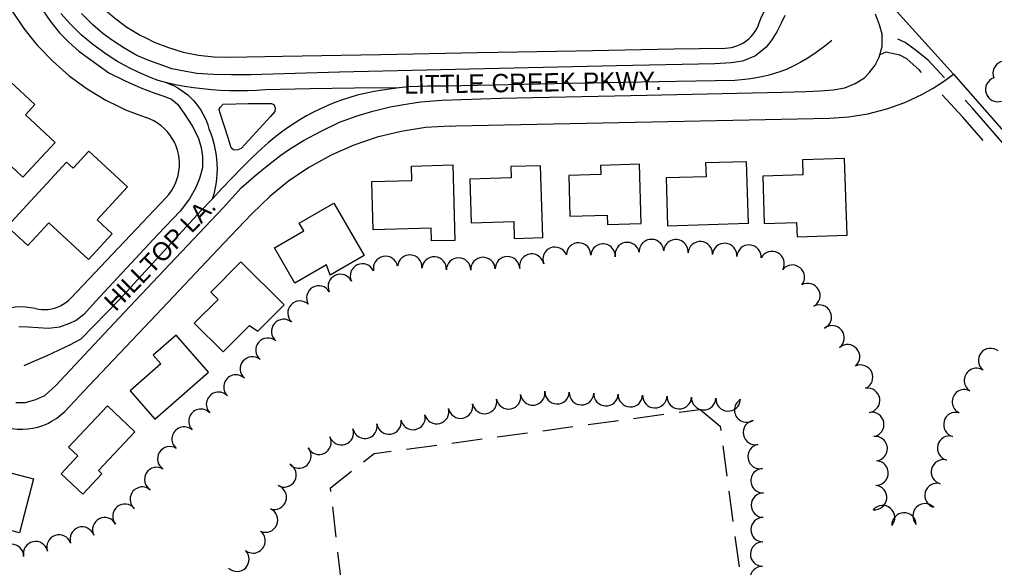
# Model space of a CAD drawing. Extents: x -25029 to 2274964, y -81170 to 687028.
# Drawn here: x -14288 to -13491, y -66632 to -66184 of the extents above; entities that cross this region are included whole.
import ezdxf

# ---------------------------------------------------------------- set-up
doc = ezdxf.new("R2010")
doc.units = 0
for name, color, linetype in [('81911BEA - RW_X_Fee_RW', 7, 'Continuous'), ('BLDG', 7, 'Continuous'), ('DRIVWY', 7, 'Continuous'), ('GE_X_CL_2000', 7, 'Continuous'), ('RECREATION', 7, 'Continuous'), ('ROAD', 7, 'Continuous'), ('ROAD-NAME', 7, 'Continuous'), ('TREES', 7, 'Continuous')]:
    doc.layers.add(name, color=color, linetype=linetype)

msp = doc.modelspace()

# ---------------------------------------------------------------- linework, layer by layer
at = {"layer": '81911BEA - RW_X_Fee_RW'}
for p, q in [((-13581.33, -66165.9), (-13524.59, -66228.63)), ((-14246.44, -66411.89), (-14168.5, -66329.68))]:
    msp.add_line(p, q, dxfattribs=at)
for points in [[(-14324.71, -66074), (-14323.56, -66091.93), (-14320.84, -66109.69), (-14316.58, -66127.14), (-14313.09, -66137.43), (-14310.81, -66144.16), (-14303.57, -66160.6), (-14294.91, -66176.35), (-14284.91, -66191.27), (-14276.29, -66201.99), (-14273.64, -66205.27), (-14261.19, -66218.22), (-14247.66, -66230.04), (-14233.14, -66240.62), (-14217.75, -66249.89), (-14207.78, -66254.76), (-14201.6, -66257.78), (-14184.83, -66264.23)], [(-14264.73, -66072.77), (-14263.92, -66085.4), (-14262.01, -66097.9), (-14259.02, -66110.19), (-14254.97, -66122.18), (-14249.89, -66133.76), (-14243.82, -66144.86), (-14236.81, -66155.39), (-14228.9, -66165.27), (-14220.17, -66174.42), (-14210.67, -66182.77), (-14200.48, -66190.26), (-14189.67, -66196.84), (-14184.53, -66199.38), (-14178.33, -66202.45), (-14166.55, -66207.05), (-14154.41, -66210.61), (-14142.01, -66213.09), (-14129.43, -66214.49), (-14116.79, -66214.78)], [(-13683.42, -66186.81), (-13681.55, -66181.9), (-13679.27, -66177.17), (-13676.58, -66172.66), (-13673.51, -66168.41), (-13670.07, -66164.44), (-13666.31, -66160.78), (-13662.23, -66157.47), (-13657.89, -66154.52), (-13653.3, -66151.97), (-13648.51, -66149.83), (-13643.54, -66148.11), (-13638.45, -66146.84), (-13633.27, -66146.01), (-13628.03, -66145.65), (-13622.78, -66145.74), (-13617.56, -66146.29), (-13612.41, -66147.29), (-13607.36, -66148.74), (-13602.46, -66150.62), (-13597.75, -66152.93), (-13593.25, -66155.64), (-13589.01, -66158.73), (-13584.92, -66162.07)], [(-13711.29, -66207.39), (-13708.66, -66207.22), (-13706.05, -66206.82), (-13703.49, -66206.19), (-13700.99, -66205.34), (-13698.58, -66204.28), (-13696.27, -66203), (-13694.08, -66201.53), (-13692.03, -66199.87), (-13690.13, -66198.04), (-13688.4, -66196.05), (-13686.86, -66193.91), (-13685.5, -66191.65), (-13684.35, -66189.27), (-13683.42, -66186.81)], [(-14116.79, -66214.78), (-14073.21, -66213.99), (-13993.23, -66212.53), (-13913.24, -66211.07), (-13833.25, -66209.61), (-13753.26, -66208.15), (-13711.29, -66207.39)], [(-13549.93, -66245.05), (-13541.16, -66240.08), (-13532.71, -66234.6), (-13524.59, -66228.63)], [(-13524.59, -66228.63), (-13386.09, -66386.37), (-13201.11, -66597.05)], [(-13626.11, -66264.78), (-13614.4, -66263.99), (-13610.27, -66263.71), (-13594.6, -66261.18), (-13579.23, -66257.2), (-13564.3, -66251.81), (-13549.93, -66245.05)], [(-14168.5, -66329.68), (-14166.22, -66327.04), (-14164.17, -66324.22), (-14162.37, -66321.23), (-14160.84, -66318.09), (-14159.59, -66314.84), (-14158.63, -66311.48), (-14157.97, -66308.06), (-14157.6, -66304.59), (-14157.54, -66301.1), (-14157.79, -66297.62), (-14158.33, -66294.18), (-14159.18, -66290.79), (-14160.31, -66287.49), (-14161.73, -66284.31), (-14163.43, -66281.26), (-14165.38, -66278.36), (-14167.57, -66275.65), (-14170, -66273.14), (-14172.63, -66270.85), (-14175.45, -66268.8), (-14178.44, -66267.01), (-14181.58, -66265.48), (-14184.83, -66264.23)], [(-13936.07, -66271.11), (-13931.54, -66271.02), (-13851.56, -66269.38), (-13771.57, -66267.75), (-13691.59, -66266.11), (-13626.11, -66264.78)], [(-13936.07, -66271.11), (-13956.25, -66272.41), (-13976.23, -66275.48), (-13995.88, -66280.29), (-14015.02, -66286.81), (-14033.52, -66294.99), (-14043.9, -66300.72), (-14051.22, -66304.76), (-14068, -66316.05), (-14083.72, -66328.76), (-14098.27, -66342.81)], [(-14251.43, -66504.36), (-14231.51, -66483.34), (-14176.46, -66425.29), (-14121.42, -66367.23), (-14098.27, -66342.81)], [(-14275.21, -66420.42), (-14272.64, -66420.92), (-14270.03, -66421.19), (-14267.42, -66421.23), (-14264.81, -66421.05), (-14262.22, -66420.64), (-14259.68, -66420.01), (-14257.21, -66419.15), (-14254.82, -66418.09), (-14252.53, -66416.82), (-14250.36, -66415.35), (-14248.32, -66413.7), (-14246.44, -66411.89)], [(-14275.21, -66420.42), (-14279.34, -66419.61), (-14283.53, -66419.15), (-14287.74, -66419.05), (-14291.95, -66419.3), (-14296.12, -66419.9), (-14300.22, -66420.86), (-14304.23, -66422.15), (-14308.12, -66423.78), (-14311.85, -66425.73), (-14315.41, -66427.99), (-14318.71, -66430.5)], [(-14298.61, -66517.63), (-14294.43, -66518.45), (-14290.19, -66518.92), (-14285.92, -66519.02), (-14281.66, -66518.76), (-14277.44, -66518.14), (-14273.29, -66517.16), (-14269.23, -66515.83), (-14265.3, -66514.17), (-14261.53, -66512.17), (-14257.95, -66509.85), (-14254.57, -66507.25), (-14251.43, -66504.36)]]:
    msp.add_lwpolyline(points, dxfattribs=at)
at = {"layer": 'BLDG'}
for points in [[(-14299.71, -66231.19), (-14275.69, -66253.65), (-14283.37, -66261.86), (-14259.2, -66284.46), (-14285.76, -66312.87), (-14333.95, -66267.81)], [(-14281.61, -66368.73), (-14264.46, -66350.18), (-14232.02, -66380.18), (-14212.56, -66359.13), (-14224.87, -66347.74), (-14200.02, -66320.87), (-14231.64, -66291.62), (-14244.58, -66305.62), (-14249.86, -66300.73), (-14298.39, -66353.21)], [(-13813.22, -66303.42), (-13812.98, -66310.85), (-13839.29, -66311.66), (-13838.26, -66344.81), (-13807.74, -66343.86), (-13807.5, -66351.65), (-13779.89, -66350.79), (-13781.39, -66302.43)], [(-13693.82, -66300.3), (-13727.31, -66301.34), (-13726.96, -66312.56), (-13759.56, -66313.57), (-13758.35, -66352.66), (-13692.26, -66350.6)], [(-13648.21, -66298.68), (-13647.83, -66311.05), (-13680.56, -66312.07), (-13679.36, -66350.7), (-13652.91, -66349.88), (-13652.54, -66361.61), (-13611.68, -66360.34), (-13613.63, -66297.6)], [(-14000.23, -66316.35), (-13967.57, -66315.52), (-13967.86, -66303.82), (-13933.91, -66302.95), (-13932.34, -66364.59), (-13951.57, -66365.08), (-13951.83, -66354.68), (-13999.22, -66355.89)], [(-13886.64, -66304.3), (-13886.35, -66313.44), (-13920.01, -66314.48), (-13918.9, -66350.2), (-13884.21, -66349.12), (-13883.78, -66362.97), (-13860.4, -66362.24), (-13862.22, -66303.54)], [(-14055.97, -66356.92), (-14059.66, -66350.55), (-14031.42, -66334.17), (-14006.61, -66376.93), (-14034.44, -66393.06), (-14037.42, -66384.72), (-14063.16, -66399.65), (-14079.9, -66370.8)], [(-14132.04, -66406.82), (-14126.04, -66412.81), (-14145.43, -66432.22), (-14121.84, -66455.8), (-14100.17, -66434.1), (-14093.47, -66438.69), (-14072.02, -66417.21), (-14107.25, -66382.01)], [(-14179.05, -66458.43), (-14172.77, -66465.63), (-14197.84, -66487.51), (-14177.66, -66510.63), (-14133.79, -66472.33), (-14160.25, -66442.02)], [(-14193.98, -66521.1), (-14223.8, -66552.73), (-14221.01, -66555.36), (-14236.68, -66571.99), (-14254.33, -66555.34), (-14240.61, -66540.78), (-14248.17, -66533.65), (-14216.41, -66499.95)], [(-14318.47, -66525.26), (-14325.88, -66553.96), (-14307.67, -66558.66), (-14307.5, -66551.65), (-14276.86, -66559.55), (-14288.25, -66603.7), (-14339.04, -66590.6), (-14342.06, -66602.3), (-14367.94, -66595.63), (-14347.84, -66517.69)]]:
    msp.add_lwpolyline(points, close=True, dxfattribs=at)
at = {"layer": 'DRIVWY'}
for points in [[(-13531.97, -66231.63), (-13545.18, -66217.24), (-13555.84, -66208.81), (-13564.24, -66202.92), (-13570.24, -66200.13)], [(-13550.64, -66227.25), (-13552.55, -66225.17), (-13562.77, -66216.11), (-13568.58, -66213.07), (-13579.92, -66210.86), (-13584.9, -66212.93)], [(-13500.38, -66282.91), (-13517.02, -66263.9), (-13533.74, -66245.67)], [(-13481.98, -66287.54), (-13509.02, -66256.64), (-13515.06, -66250.05)]]:
    msp.add_lwpolyline(points, dxfattribs=at)
at = {"layer": 'GE_X_CL_2000'}
for points in [[(-14167.89, -66235.78), (-14174.86, -66233.78), (-14180.63, -66231.67), (-14186.32, -66229.36), (-14191.94, -66226.87), (-14197.47, -66224.19), (-14202.9, -66221.33), (-14208.24, -66218.28), (-14213.47, -66215.06), (-14218.59, -66211.67), (-14223.6, -66208.11), (-14228.48, -66204.39), (-14233.24, -66200.5), (-14237.86, -66196.46), (-14242.34, -66192.27), (-14246.68, -66187.93), (-14254.66, -66179.12)], [(-13624.02, -66201.17), (-13628.84, -66205.13), (-13633.81, -66208.89), (-13638.92, -66212.46), (-13644.17, -66215.82), (-13649.55, -66218.98), (-13655.05, -66221.92), (-13660.66, -66224.64), (-13665.83, -66226.53), (-13671.07, -66228.22), (-13676.37, -66229.7), (-13681.73, -66230.97), (-13687.13, -66232.01), (-13692.57, -66232.84), (-13698.04, -66233.46), (-13703.53, -66233.85), (-13751.17, -66234.67), (-13837.9, -66236.31), (-13939.14, -66238.61), (-13946.9, -66238.43), (-13954.67, -66238.47), (-13962.43, -66238.73), (-13970.18, -66239.21), (-13977.91, -66239.9)], [(-14167.89, -66235.78), (-14161.81, -66238.4), (-14158.9, -66239.98), (-14156.09, -66241.73), (-14153.39, -66243.65), (-14150.81, -66245.74), (-14148.36, -66247.97), (-14146.05, -66250.35), (-14143.89, -66252.87), (-14141.88, -66255.51), (-14140.05, -66258.27), (-14138.38, -66261.14), (-14136.88, -66264.1), (-14135.57, -66267.15), (-14134.45, -66270.27), (-14133.52, -66273.45), (-14131.96, -66277.35), (-14130.6, -66281.32), (-14129.45, -66285.35), (-14128.5, -66289.44), (-14127.77, -66293.57), (-14127.24, -66297.73), (-14126.93, -66301.92), (-14126.84, -66306.11), (-14126.95, -66310.31), (-14127.28, -66314.49), (-14127.83, -66318.65), (-14128.59, -66322.78), (-14129.55, -66326.86), (-14130.73, -66330.88)], [(-13977.91, -66239.9), (-14014.35, -66240.22), (-14050.79, -66240.76), (-14087.21, -66241.54), (-14094.58, -66242.05), (-14101.95, -66242.36), (-14109.34, -66242.46), (-14116.72, -66242.35), (-14124.1, -66242.04), (-14131.46, -66241.51), (-14138.81, -66240.78), (-14146.13, -66239.84), (-14153.42, -66238.69), (-14160.68, -66237.34), (-14167.89, -66235.78)], [(-13977.91, -66239.9), (-13993.31, -66241.95), (-13999.62, -66243.08), (-14005.89, -66244.44), (-14012.11, -66246), (-14018.27, -66247.79), (-14024.37, -66249.79), (-14030.39, -66251.99), (-14036.33, -66254.41), (-14042.19, -66257.03), (-14047.95, -66259.85), (-14053.61, -66262.86), (-14059.16, -66266.08), (-14064.59, -66269.48), (-14069.91, -66273.07), (-14075.09, -66276.84), (-14080.15, -66280.79), (-14085.06, -66284.91), (-14089.83, -66289.2), (-14098.33, -66297.21), (-14106.67, -66305.39), (-14114.85, -66313.73), (-14122.87, -66322.23), (-14130.73, -66330.88)], [(-14130.73, -66330.88), (-14139.68, -66340.19), (-14206.77, -66413.19), (-14238.29, -66445.44), (-14247.44, -66450.16), (-14256.67, -66454.69), (-14266, -66459.04), (-14275.42, -66463.19), (-14284.91, -66467.14)]]:
    msp.add_lwpolyline(points, dxfattribs=at)
at = {"layer": 'RECREATION'}
for p, q in [((-13786.2, -66510.15), (-13761.43, -66506.79)), ((-13749.04, -66505.11), (-13731.89, -66502.78)), ((-13860.52, -66520.23), (-13835.75, -66516.87)), ((-13823.36, -66515.19), (-13798.59, -66511.83)), ((-13897.68, -66525.27), (-13872.91, -66521.91)), ((-13972, -66535.35), (-13947.23, -66531.99)), ((-13934.84, -66530.31), (-13910.07, -66526.95)), ((-13713.3, -66532.45), (-13709.97, -66557.23)), ((-13708.3, -66569.62), (-13704.97, -66594.39)), ((-14029.39, -66607.14), (-14032.25, -66582.31)), ((-13703.31, -66606.78), (-13699.98, -66631.56)), ((-14025.09, -66644.4), (-14027.96, -66619.56))]:
    msp.add_line(p, q, dxfattribs=at)
for points in [[(-13731.89, -66502.78), (-13715.44, -66516.54), (-13714.97, -66520.06)], [(-14006.95, -66545.62), (-13998.39, -66538.93), (-13984.38, -66537.03)], [(-14033.68, -66569.89), (-14034.04, -66566.79), (-14016.8, -66553.32)]]:
    msp.add_lwpolyline(points, dxfattribs=at)
at = {"layer": 'ROAD'}
for points in [[(-14269.03, -66176.97), (-14263.02, -66185.79), (-14255.79, -66194.92), (-14248.23, -66202.18), (-14239.74, -66210.05), (-14225.1, -66220.66), (-14215.29, -66227.68), (-14202.07, -66234.28), (-14189.27, -66240.01), (-14177.73, -66244.33), (-14170.27, -66246.74), (-14164.11, -66249.27), (-14159.07, -66253.22), (-14153.61, -66260.8), (-14146.57, -66271.81), (-14142.1, -66281.31), (-14139.89, -66288.74), (-14138.68, -66295.92), (-14138.83, -66305.24), (-14141.13, -66314.08), (-14144.12, -66321.24), (-14149.26, -66330.73), (-14156.94, -66340.6), (-14175.24, -66359.68), (-14226.13, -66414.58), (-14235.7, -66425.2), (-14242.11, -66430.03), (-14248.31, -66432.78), (-14255.75, -66435.57), (-14264.67, -66436.58), (-14273.04, -66436.17), (-14281.56, -66435.46), (-14288.93, -66435.22)], [(-13662.56, -66180.72), (-13665.53, -66187.01), (-13668.94, -66194.01), (-13673.29, -66200.71), (-13677.84, -66206.53), (-13686.54, -66213.62), (-13697.27, -66218.14), (-13706.48, -66219.51), (-13719.8, -66220.28), (-13800.08, -66222), (-13920.14, -66224.67), (-14026.75, -66227.21), (-14099.23, -66229.26), (-14115.14, -66229.32), (-14129.66, -66229.12), (-14143.23, -66228.23), (-14153.74, -66226.31), (-14163.81, -66224.27), (-14171.12, -66221.71), (-14182.74, -66217.68), (-14192.33, -66213.55), (-14202.31, -66207.75), (-14212.21, -66201.3), (-14220.16, -66195.4), (-14228.31, -66188.41), (-14237.78, -66179.01)], [(-14026.56, -66267.99), (-14012.19, -66262.76), (-13999.53, -66259.08), (-13985.2, -66255.52), (-13970.9, -66252.96), (-13960.45, -66251.26), (-13943.07, -66249.93), (-13894.75, -66248.25), (-13775.49, -66245.79), (-13664.55, -66243.56), (-13645.3, -66243), (-13633.65, -66242.34), (-13623.08, -66241.43), (-13613.42, -66239.78), (-13604.95, -66236.29), (-13597.47, -66231.77), (-13593.69, -66227.67), (-13588.77, -66221.28), (-13585.44, -66214.85), (-13582.99, -66206.09), (-13583.04, -66196.11), (-13585.1, -66188.33), (-13588.36, -66179.58)], [(-14291.4, -66497.04), (-14283.44, -66497.01), (-14275.07, -66494.6), (-14267.77, -66491.38), (-14258.54, -66483.28), (-14235.47, -66458.38), (-14202.55, -66423.37), (-14165.63, -66384.2), (-14121.82, -66337.88), (-14107.12, -66321.6), (-14094.58, -66310.77), (-14084.55, -66302.69), (-14074.54, -66295.05), (-14067.56, -66290.15), (-14056.04, -66282.83), (-14041.62, -66275.29), (-14026.56, -66267.99)]]:
    msp.add_lwpolyline(points, dxfattribs=at)
msp.add_lwpolyline([(-14101.3, -66252.78), (-14082.22, -66252.58), (-14080.29, -66253.64), (-14079.41, -66256.19), (-14079.7, -66259.22), (-14083.12, -66263.4), (-14107.15, -66289.36), (-14109.93, -66290.6), (-14113.19, -66290.74), (-14115.17, -66289.03), (-14117.8, -66280.87), (-14124.6, -66259.75), (-14124.98, -66257.28), (-14124.22, -66255.93), (-14121.84, -66253.16)], close=True, dxfattribs=at)
at = {"layer": 'TREES'}
for centre, start, end in [((-13482.31, -66227.92), 22.60913, 202.60913), ((-13488.43, -66241.27), 108.17007, 288.17007), ((-13831.14, -66376.52), 359.03704, 179.03704), ((-13791.37, -66376.24), 10.9669, 190.9669), ((-13771.58, -66373.73), 3.46887, 183.46887), ((-13751.63, -66373.93), 355.39339, 175.39339), ((-13731.69, -66375.47), 355.75903, 175.75903), ((-13850.41, -66380.08), 21.91223, 201.91223), ((-13811.17, -66377.41), 355.83641, 175.83641), ((-13711.74, -66376.95), 355.75903, 175.75903), ((-13691.79, -66378.31), 356.43294, 176.43294), ((-13672.98, -66383.63), 332.01492, 152.01492), ((-13989.02, -66387.61), 10.77424, 190.77424), ((-13969.22, -66386.5), 355.61782, 175.61782), ((-13949.28, -66388.03), 355.61782, 175.61782), ((-13929.31, -66388.85), 359.66737, 179.66737), ((-13909.32, -66388.43), 2.74402, 182.74402), ((-13889.33, -66387.76), 1.09303, 181.09303), ((-13869.51, -66385.69), 10.81908, 190.81908), ((-14007.88, -66393.74), 25.24584, 205.24584), ((-13656.43, -66394.68), 320.53271, 140.53271), ((-14025.97, -66402.27), 25.24584, 205.24584), ((-14043.6, -66411.68), 30.94459, 210.94459), ((-13643.69, -66409.69), 300.07669, 120.07669), ((-14059.02, -66424.11), 46.79638, 226.79638), ((-13634.37, -66427.36), 295.57009, 115.57009), ((-14072.29, -66439.06), 50.00542, 230.00542), ((-13623.92, -66444.28), 307.81261, 127.81261), ((-14085.15, -66454.38), 50.00542, 230.00542), ((-13611.25, -66459.75), 310.7958, 130.7958), ((-13494.26, -66462.86), 52.47631, 232.47631), ((-14098, -66469.7), 50.00542, 230.00542), ((-13600.58, -66476.42), 294.46406, 114.46406), ((-13505.86, -66479.13), 56.58168, 236.58168), ((-14111.41, -66484.52), 45.71734, 225.71734), ((-13594.84, -66495.4), 279.19365, 99.19365), ((-14125.6, -66498.61), 43.87047, 223.87047), ((-13888.4, -66492.52), 190.9008, 10.9008), ((-13868.67, -66489.29), 187.68418, 7.68418), ((-13848.77, -66488.35), 177.71804, 357.71804), ((-13828.78, -66489.15), 177.71804, 357.71804), ((-13808.8, -66489.94), 177.71804, 357.71804), ((-13788.82, -66490.74), 177.71804, 357.71804), ((-13768.83, -66491.53), 177.71804, 357.71804), ((-13748.85, -66492.33), 177.71804, 357.71804), ((-13728.86, -66493.13), 177.71804, 357.71804), ((-13708.89, -66494.16), 176.35814, 356.35814), ((-13515.68, -66496.5), 64.42026, 244.42026), ((-13947.16, -66504.55), 194.96492, 14.96492), ((-13927.68, -66500.08), 190.9008, 10.9008), ((-13908.04, -66496.3), 190.9008, 10.9008), ((-13693.68, -66503.32), 121.53921, 301.53921), ((-14140.02, -66512.47), 43.87047, 223.87047), ((-13966.57, -66509.37), 192.88382, 12.88382), ((-13591.44, -66515.1), 280.40597, 100.40597), ((-13522.66, -66515.16), 74.56579, 254.56579), ((-14153.71, -66527.02), 49.56964, 229.56964), ((-14005.9, -66516.53), 191.6584, 11.6584), ((-13986.21, -66513.05), 188.37485, 8.37485), ((-13686.55, -66521.66), 100.9274, 280.9274), ((-14043.5, -66529.64), 206.7851, 26.7851), ((-14025.13, -66521.84), 199.21958, 19.21958), ((-13588.64, -66534.89), 275.66285, 95.66285), ((-13527.83, -66534.48), 75.44856, 255.44856), ((-14165.48, -66543.12), 58.12027, 238.12027), ((-13682.76, -66541.3), 100.9274, 280.9274), ((-14059.87, -66540.83), 221.92504, 41.92504), ((-14072.08, -66556.3), 241.47583, 61.47583), ((-13587.89, -66554.84), 268.64885, 88.64885), ((-13532.86, -66553.84), 75.44856, 255.44856), ((-14176.12, -66560.05), 57.59094, 237.59094), ((-13680.35, -66561.1), 92.94519, 272.94519), ((-14080.04, -66574.56), 251.47094, 71.47094), ((-13589.14, -66574.79), 264.16797, 84.16797), ((-13538.03, -66573.16), 74.55644, 254.55644), ((-14187.91, -66576.16), 49.9932, 229.9932), ((-13680, -66581.09), 89.05938, 269.05938), ((-14202.06, -66590.17), 39.44428, 219.44428), ((-13582.58, -66591.25), 319.31499, 139.31499), ((-13547.86, -66589.77), 44.25943, 224.25943), ((-14087.21, -66593.21), 246.46533, 66.46533), ((-13565.01, -66597.26), 2.92108, 182.92108), ((-14218.7, -66601.05), 26.90545, 206.90545), ((-13680.33, -66601.09), 89.05938, 269.05938), ((-14256, -66615.29), 18.90623, 198.90623), ((-14237.08, -66608.81), 18.90623, 198.90623), ((-14097.41, -66610.22), 231.63885, 51.63885), ((-14294.98, -66622.87), 359.84555, 179.84555), ((-14275.22, -66620.71), 12.5978, 192.5978), ((-13680.66, -66621.08), 89.05938, 269.05938), ((-14110.57, -66625.25), 225.91856, 45.91856), ((-13680.99, -66641.08), 89.05938, 269.05938)]:
    msp.add_arc(centre, 10, start, end, dxfattribs=at)

# ---------------------------------------------------------------- texts
at = {"layer": 'ROAD-NAME'}
for s, rotation, p in [('LITTLE CREEK PKWY.', 0.8857, (-13973.57, -66244.76)), ('HILLTOP LA.', 45.7752, (-14209.82, -66423.36))]:
    msp.add_text(s, height=15, rotation=rotation, dxfattribs=at).set_placement(p)

doc.saveas('drawing.dxf')
